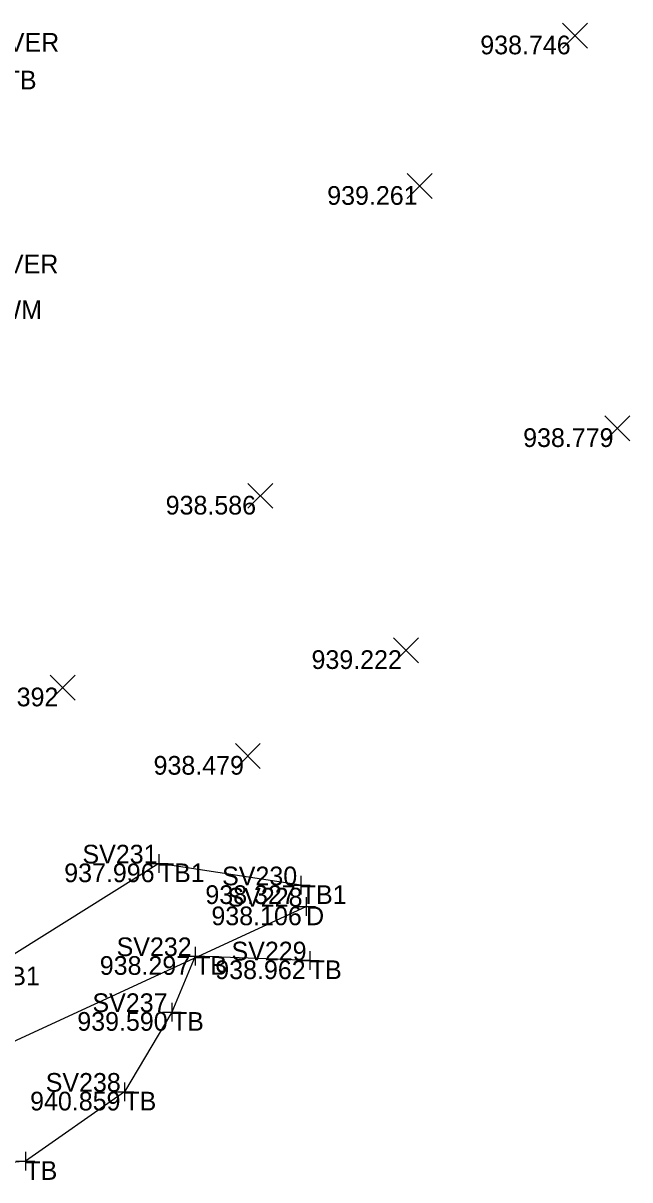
# Model space of a CAD drawing. Extents: x 2262025 to 2264532, y 740981 to 742724.
# Drawn here: x 2263177.3 to 2263209.8, y 742446.1 to 742508 of the extents above; entities that cross this region are included whole.
import ezdxf

# ---------------------------------------------------------------- set-up
doc = ezdxf.new("R2010")
doc.units = 0
for name, color, linetype in [('GE_X_Alignment_1000_Stations', 7, 'Continuous'), ('GE_X_Alignment_100_Distances', 7, 'Continuous'), ('GE_X_Alignment_500_Cardinal_Points', 7, 'Continuous'), ('HY_X_Spring_Cells', 7, 'Continuous'), ('RW_X_CL', 7, 'Continuous'), ('RW_X_CL_100_Cardinal_Points', 7, 'Continuous'), ('SV_X_Text_Comment', 7, 'Continuous')]:
    doc.layers.add(name, color=color, linetype=linetype)

msp = doc.modelspace()

# ---------------------------------------------------------------- linework, layer by layer
at = {"layer": 'GE_X_Alignment_1000_Stations'}
for points in [[(2263192.181, 742461.856), (2263184.59, 742463.024), (2263175.771, 742457.504), (2263170.425, 742452.081), (2263164.676, 742453.234), (2263162.833, 742454.118)], [(2263192.664, 742457.838), (2263186.532, 742458.066), (2263185.287, 742455.074), (2263182.743, 742450.811), (2263177.447, 742447.096), (2263174.206, 742446.766), (2263169.56, 742447.866)]]:
    msp.add_lwpolyline(points, dxfattribs=at)
at = {"layer": 'GE_X_Alignment_100_Distances'}
msp.add_lwpolyline([(2263162.45, 742452.423), (2263169.804, 742450.277), (2263192.466, 742460.72)], dxfattribs=at)
at = {"layer": 'GE_X_Alignment_500_Cardinal_Points'}
for p, q in [((2263206.18, 742506.649), (2263207.514, 742507.984)), ((2263206.18, 742507.984), (2263207.514, 742506.649)), ((2263197.87, 742498.596), (2263199.204, 742499.931)), ((2263197.87, 742499.931), (2263199.204, 742498.596)), ((2263208.452, 742485.64), (2263209.786, 742486.975)), ((2263208.452, 742486.975), (2263209.786, 742485.64)), ((2263189.351, 742482.026), (2263190.685, 742483.361)), ((2263189.351, 742483.361), (2263190.685, 742482.026)), ((2263197.145, 742473.764), (2263198.479, 742475.099)), ((2263197.145, 742475.099), (2263198.479, 742473.764)), ((2263178.77, 742471.766), (2263180.104, 742473.101)), ((2263178.77, 742473.101), (2263180.104, 742471.766)), ((2263188.681, 742468.108), (2263190.015, 742469.443)), ((2263188.681, 742469.443), (2263190.015, 742468.108))]:
    msp.add_line(p, q, dxfattribs=at)
at = {"layer": 'RW_X_CL_100_Cardinal_Points'}
for p, q in [((2263184.59, 742463.524), (2263184.59, 742462.524)), ((2263184.09, 742463.024), (2263185.09, 742463.024)), ((2263184.59, 742463.024), (2263184.59, 742463.024)), ((2263192.181, 742462.356), (2263192.181, 742461.356)), ((2263191.681, 742461.856), (2263192.681, 742461.856)), ((2263192.181, 742461.856), (2263192.181, 742461.856)), ((2263191.966, 742460.72), (2263192.966, 742460.72)), ((2263192.466, 742461.22), (2263192.466, 742460.22)), ((2263192.466, 742460.72), (2263192.466, 742460.72)), ((2263186.532, 742458.566), (2263186.532, 742457.566)), ((2263192.664, 742458.338), (2263192.664, 742457.338)), ((2263186.032, 742458.066), (2263187.032, 742458.066)), ((2263186.532, 742458.066), (2263186.532, 742458.066)), ((2263192.164, 742457.838), (2263193.164, 742457.838)), ((2263192.664, 742457.838), (2263192.664, 742457.838)), ((2263184.787, 742455.074), (2263185.787, 742455.074)), ((2263185.287, 742455.574), (2263185.287, 742454.574)), ((2263185.287, 742455.074), (2263185.287, 742455.074)), ((2263182.243, 742450.811), (2263183.243, 742450.811)), ((2263182.743, 742451.311), (2263182.743, 742450.311)), ((2263182.743, 742450.811), (2263182.743, 742450.811)), ((2263176.947, 742447.096), (2263177.947, 742447.096)), ((2263177.447, 742447.596), (2263177.447, 742446.596)), ((2263177.447, 742447.096), (2263177.447, 742447.096))]:
    msp.add_line(p, q, dxfattribs=at)

# ---------------------------------------------------------------- texts
at = {"layer": 'HY_X_Spring_Cells'}
for s, p in [('938.746', (2263201.783, 742506.316)), ('939.261', (2263193.596, 742498.263)), ('938.779', (2263204.078, 742485.307)), ('938.586', (2263184.954, 742481.693)), ('939.222', (2263192.756, 742473.431)), ('938.392', (2263174.381, 742471.433)), ('938.479', (2263184.307, 742467.775)), ('937.996', (2263179.526, 742462.024)), ('938.327', (2263187.078, 742460.856)), ('938.106', (2263187.402, 742459.72)), ('938.297', (2263181.429, 742457.066)), ('938.962', (2263187.608, 742456.838)), ('939.590', (2263180.226, 742454.074)), ('940.859', (2263177.702, 742449.811))]:
    msp.add_text(s, height=1, dxfattribs=at).set_placement(p)
at = {"layer": 'RW_X_CL'}
for s, p in [('RIVER', (2263175.171, 742506.454)), ('TB', (2263176.338, 742504.44)), ('RIVER', (2263175.127, 742494.598)), ('OHWM', (2263173.955, 742492.152)), ('TB1', (2263184.59, 742462.024)), ('TB1', (2263192.181, 742460.856)), ('D', (2263192.466, 742459.72)), ('TB', (2263186.532, 742457.066)), ('TB', (2263192.664, 742456.838)), ('TB1', (2263175.771, 742456.504)), ('TB', (2263185.287, 742454.074)), ('TB', (2263182.743, 742449.811)), ('TB', (2263177.447, 742446.096))]:
    msp.add_text(s, height=1, dxfattribs=at).set_placement(p)
at = {"layer": 'SV_X_Text_Comment'}
for s, p in [('SV231', (2263180.503, 742463.024)), ('SV230', (2263187.974, 742461.856)), ('SV228', (2263188.26, 742460.72)), ('SV232', (2263182.329, 742458.066)), ('SV229', (2263188.476, 742457.838)), ('SV237', (2263181.038, 742455.074)), ('SV238', (2263178.537, 742450.811))]:
    msp.add_text(s, height=1, dxfattribs=at).set_placement(p)

doc.saveas('drawing.dxf')
